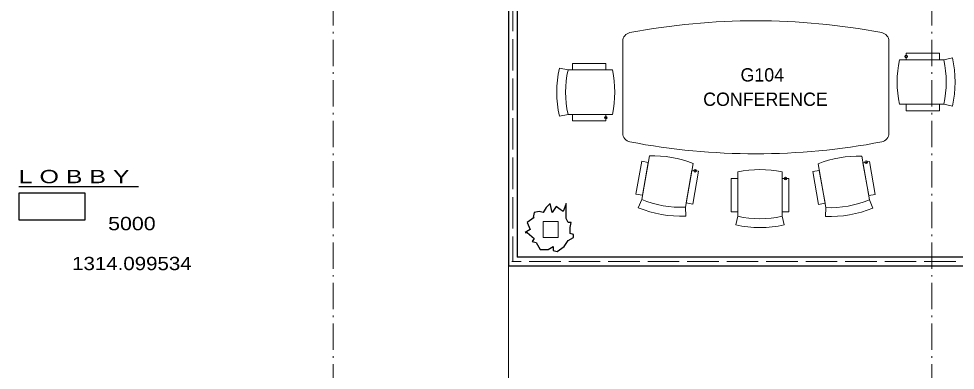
# Model space of a CAD drawing. Extents: x -118748 to -117136, y -118748 to -117596.
# Drawn here: x -118019.7 to -117681.9, y -118332.8 to -118206 of the extents above; entities that cross this region are included whole.
import ezdxf
from ezdxf.enums import TextEntityAlignment as Align

# ---------------------------------------------------------------- set-up
doc = ezdxf.new("R2010")
doc.units = 0
doc.header["$LTSCALE"] = 1.9
doc.header["$PDMODE"] = 32
doc.header["$PDSIZE"] = 0.95
doc.linetypes.add('DOT_DASHED', pattern=[7.7, 5, -1.2, 0.3, -1.2])
doc.linetypes.add('LONG_DASHED', pattern=[7.5, 6, -1.5])
for name, color, linetype, lineweight in [('10', 7, 'DOT_DASHED', 13), ('15', 7, 'Continuous', 13), ('17', 7, 'Continuous', 25), ('23', 7, 'Continuous', 25), ('45', 7, 'Continuous', 25), ('5', 7, 'Continuous', 13), ('6', 7, 'Continuous', 13), ('60', 7, 'LONG_DASHED', 13), ('9', 7, 'Continuous', 35)]:
    doc.layers.add(name, color=color, linetype=linetype, lineweight=lineweight)
doc.layers.add('53', color=7, linetype='Continuous')

msp = doc.modelspace()

# ---------------------------------------------------------------- linework, layer by layer
at = {"layer": '10'}
for p, q in [((-117906.321, -117628.339), (-117906.321, -118698.41)), ((-117690.321, -117628.339), (-117690.321, -118698.41))]:
    msp.add_line(p, q, dxfattribs=at)
at = {"layer": '15'}
for p, q in [((-117801.814, -118214.137), (-117801.814, -118247.272)), ((-117705.814, -118214.137), (-117705.814, -118247.272)), ((-117699.589, -118218.422), (-117687.589, -118218.422)), ((-117699.589, -118220.822), (-117699.589, -118218.422)), ((-117687.589, -118218.422), (-117687.589, -118220.822)), ((-117685.989, -118220.822), (-117682.861, -118220.145)), ((-117807.957, -118222.077), (-117819.957, -118222.077)), ((-117819.957, -118224.477), (-117819.957, -118222.077)), ((-117807.957, -118222.077), (-117807.957, -118224.477)), ((-117701.989, -118220.822), (-117685.989, -118220.822)), ((-117699.589, -118220.822), (-117687.589, -118220.822)), ((-117821.557, -118224.477), (-117824.685, -118223.801)), ((-117805.557, -118224.477), (-117821.557, -118224.477)), ((-117807.957, -118224.477), (-117819.957, -118224.477)), ((-117701.989, -118236.822), (-117685.989, -118236.822)), ((-117699.589, -118236.822), (-117687.589, -118236.822)), ((-117699.589, -118239.221), (-117699.589, -118236.822)), ((-117687.589, -118236.822), (-117687.589, -118239.221)), ((-117685.989, -118236.822), (-117682.861, -118237.498)), ((-117699.589, -118239.221), (-117687.589, -118239.221)), ((-117821.557, -118240.477), (-117824.685, -118241.153)), ((-117805.557, -118240.477), (-117821.557, -118240.477)), ((-117807.957, -118240.477), (-117819.957, -118240.477)), ((-117819.957, -118242.877), (-117819.957, -118240.477)), ((-117807.957, -118242.877), (-117819.957, -118242.877)), ((-117807.957, -118240.477), (-117807.957, -118242.877)), ((-117792.209, -118255.464), (-117794.987, -118271.221)), ((-117715.597, -118255.596), (-117712.818, -118271.353)), ((-117794.989, -118257.41), (-117797.073, -118269.228)), ((-117794.989, -118257.41), (-117792.626, -118257.827)), ((-117792.626, -118257.827), (-117794.71, -118269.645)), ((-117776.452, -118258.242), (-117779.23, -118273.999)), ((-117776.869, -118260.605), (-117778.952, -118272.423)), ((-117776.869, -118260.605), (-117774.505, -118261.022)), ((-117731.354, -118258.374), (-117728.575, -118274.131)), ((-117715.18, -118257.96), (-117712.816, -118257.543)), ((-117715.18, -118257.96), (-117713.096, -118269.777)), ((-117712.816, -118257.543), (-117710.733, -118269.361)), ((-117774.505, -118261.022), (-117776.589, -118272.84)), ((-117762.723, -118263.666), (-117762.723, -118275.666)), ((-117762.723, -118263.666), (-117760.323, -118263.666)), ((-117760.323, -118261.266), (-117760.323, -118277.266)), ((-117760.323, -118263.666), (-117760.323, -118275.666)), ((-117744.323, -118261.266), (-117744.323, -118277.266)), ((-117744.323, -118263.666), (-117744.323, -118275.666)), ((-117744.323, -118263.666), (-117741.923, -118263.666)), ((-117741.923, -118263.666), (-117741.923, -118275.666)), ((-117733.3, -118261.155), (-117730.937, -118260.738)), ((-117733.3, -118261.155), (-117731.217, -118272.972)), ((-117730.937, -118260.738), (-117728.853, -118272.556)), ((-117794.71, -118269.645), (-117797.073, -118269.228)), ((-117710.733, -118269.361), (-117713.096, -118269.777)), ((-117794.987, -118271.221), (-117796.196, -118274.183)), ((-117779.23, -118273.999), (-117779.108, -118277.197)), ((-117776.589, -118272.84), (-117778.952, -118272.423)), ((-117728.853, -118272.556), (-117731.217, -118272.972)), ((-117728.575, -118274.131), (-117728.698, -118277.329)), ((-117712.818, -118271.353), (-117711.609, -118274.316)), ((-117760.323, -118275.666), (-117762.723, -118275.666)), ((-117760.323, -118277.266), (-117760.999, -118280.394)), ((-117741.923, -118275.666), (-117744.323, -118275.666)), ((-117744.323, -118277.266), (-117743.647, -118280.394))]:
    msp.add_line(p, q, dxfattribs=at)
for centre, radius, start, end in [((-117753.814, -118449.105), 242.4, 79.20526, 100.79472), ((-117798.614, -118214.137), 3.2, 100.79473, 180), ((-117709.014, -118214.137), 3.2, 0, 79.20527), ((-117722.997, -118228.822), 41.063, 347.80217, 12.19783), ((-117664.981, -118228.822), 37.863, 167.80217, 192.19783), ((-117722.997, -118228.822), 37.863, 347.80217, 12.19783), ((-117722.997, -118228.822), 37.863, 347.80217, 12.19783), ((-117784.548, -118232.477), 41.063, 167.80217, 192.19783), ((-117784.548, -118232.477), 37.863, 167.80217, 192.19783), ((-117784.548, -118232.477), 37.863, 167.80217, 192.19783), ((-117842.565, -118232.477), 37.863, 347.80217, 12.19783), ((-117798.614, -118247.272), 3.2, 180, 259.20527), ((-117753.814, -118012.304), 242.4, 259.20527, 280.79473), ((-117709.014, -118247.272), 3.2, 280.79473, 0), ((-117790.757, -118293.299), 37.863, 67.80218, 92.19783), ((-117717.049, -118293.431), 37.863, 87.80217, 112.19782), ((-117752.323, -118298.274), 37.863, 77.80217, 102.19782), ((-117780.682, -118236.164), 41.063, 247.80217, 272.19783), ((-117780.682, -118236.164), 37.863, 247.80217, 272.19783), ((-117780.682, -118236.164), 37.863, 247.80217, 272.19783), ((-117727.123, -118236.296), 37.863, 267.80217, 292.19782), ((-117727.123, -118236.296), 37.863, 267.80217, 292.19782), ((-117752.323, -118240.258), 37.863, 257.80217, 282.19783), ((-117752.323, -118240.258), 37.863, 257.80217, 282.19783), ((-117727.123, -118236.296), 41.063, 267.80217, 292.19782), ((-117752.323, -118240.258), 41.063, 257.80217, 282.19783)]:
    msp.add_arc(centre, radius, start, end, dxfattribs=at)
for p in [(-117699.589, -118219.622), (-117807.957, -118241.677), (-117713.998, -118257.751), (-117775.687, -118260.814), (-117743.123, -118263.666)]:
    msp.add_point(p, dxfattribs=at)
at = {"layer": '17'}
msp.add_line((-118019.691, -118266.518), (-117976.491, -118266.518), dxfattribs=at)
msp.add_lwpolyline([(-117833.757, -118277.667), (-117836.291, -118279.477), (-117835.205, -118282.012), (-117837.015, -118283.098), (-117836.291, -118283.098), (-117833.757, -118285.27), (-117834.481, -118286.356), (-117833.033, -118286.718), (-117831.584, -118289.252), (-117828.688, -118289.252), (-117826.878, -118288.166), (-117826.878, -118289.614), (-117825.43, -118289.976), (-117822.895, -118288.166), (-117821.447, -118285.994), (-117819.637, -118284.908), (-117819.637, -118283.822), (-117820.723, -118283.46), (-117820.723, -118281.287), (-117820.361, -118279.477), (-117821.447, -118279.477), (-117822.171, -118278.029), (-117822.171, -118272.599), (-117823.258, -118275.495), (-117824.344, -118274.771), (-117825.792, -118273.685), (-117827.24, -118275.857), (-117827.964, -118272.599), (-117829.412, -118274.047), (-117830.498, -118275.857), (-117831.946, -118275.495), (-117833.757, -118275.857), (-117834.119, -118277.667)], dxfattribs=at)
at = {"layer": '17', "lineweight": 13}
msp.add_lwpolyline([(-117830.498, -118279.115), (-117830.498, -118284.908), (-117825.068, -118284.908), (-117825.068, -118279.115)], close=True, dxfattribs=at)
at = {"layer": '23'}
for p, q in [((-117843.071, -118184.81), (-117843.071, -118295.21)), ((-117839.871, -118184.81), (-117839.871, -118292.01)), ((-117503.121, -118292.01), (-117839.871, -118292.01)), ((-117503.121, -118295.21), (-117843.071, -118295.21))]:
    msp.add_line(p, q, dxfattribs=at)
at = {"layer": '45'}
msp.add_lwpolyline([(-118019.691, -118268.918), (-118019.691, -118278.518), (-117995.691, -118278.518), (-117995.691, -118268.918)], close=True, dxfattribs=at)
at = {"layer": '5'}
for points in [[(-117981.521, -118118.36), (-117981.521, -117964.01), (-117469.521, -117964.01), (-117469.521, -117992.81), (-117469.521, -118180.01), (-117469.521, -118292.01), (-117839.871, -118292.01), (-117839.871, -118184.81)], [(-117843.071, -118184.81), (-117843.071, -118295.21), (-117503.121, -118295.21), (-117469.521, -118295.21), (-117469.521, -118301.61), (-117469.521, -118343.21), (-117479.121, -118343.21), (-117698.321, -118343.21), (-117698.321, -118357.61), (-117698.321, -118420.01), (-117843.25, -118420.01)]]:
    msp.add_lwpolyline(points, dxfattribs=at)
at = {"layer": '6'}
for points in [[(-117981.521, -117964.01), (-117469.521, -117964.01), (-117469.521, -118292.01), (-117839.871, -118292.01), (-117839.871, -118184.81)], [(-117843.071, -118184.81), (-117843.071, -118343.21), (-117698.321, -118343.21), (-117698.321, -118420.01), (-117843.25, -118420.01)]]:
    msp.add_lwpolyline(points, dxfattribs=at)
msp.add_lwpolyline([(-117843.071, -118295.21), (-117469.521, -118295.21), (-117469.521, -118343.21), (-117843.071, -118343.21)], close=True, dxfattribs=at)
at = {"layer": '60'}
for p, q in [((-117841.471, -118184.81), (-117841.471, -118293.61)), ((-117467.921, -118293.61), (-117841.784, -118293.61))]:
    msp.add_line(p, q, dxfattribs=at)

# ---------------------------------------------------------------- texts
at = {"layer": '17', "width": 1.4}
msp.add_text('L O B B Y', height=4.8, dxfattribs=at).set_placement((-118019.691, -118265.318))
at = {"layer": '45'}
for s, width, p in [('5000', 1.2, (-117978.876, -118282.285)), ('1314.099534', 1.15, (-117978.876, -118296.685))]:
    msp.add_text(s, height=4.8, dxfattribs=dict(at, width=width)).set_placement(p, align=Align.CENTER)
at = {"layer": '53'}
msp.add_text('CONFERENCE', height=4.8, dxfattribs=at).set_placement((-117772.803, -118237.419))
at = {"layer": '9'}
msp.add_text('G104', height=4.8, dxfattribs=at).set_placement((-117751.482, -118228.629), align=Align.CENTER)

doc.saveas('drawing.dxf')
